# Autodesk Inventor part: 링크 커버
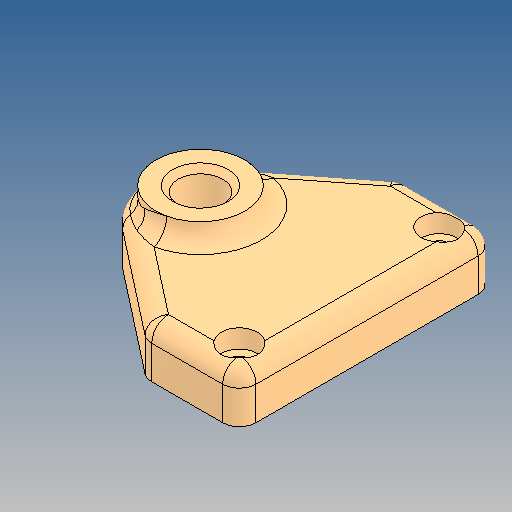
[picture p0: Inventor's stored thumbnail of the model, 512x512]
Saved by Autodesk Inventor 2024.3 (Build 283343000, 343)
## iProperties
Created: 2025-06
Part Number: 링크 커버
Material: 알루미늄 6061
Document SubType Name: Modeling
Designer: user
Density: 2.7 g/cm^3
Appearance: 기본값
Author: jhkim
Sending System: Autodesk Inventor 2026
Preprocessor: ST-DEVELOPER v20.1
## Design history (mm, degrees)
node "링크 커버1"
node "솔리드2"
node "솔리드1"
